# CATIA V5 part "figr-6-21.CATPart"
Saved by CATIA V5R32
Part number: Part1
Bounding box of the stored display mesh (mm): x 0 to 150, y -70 to 70, z -150 to 69.804
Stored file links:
  D:\PROJECTS\Project 2022\CATIA V5 6R 2022\Resources\Part Files\c06_catia_v5_6r2022_prt\figr-6-21.CATPart
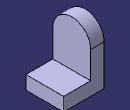
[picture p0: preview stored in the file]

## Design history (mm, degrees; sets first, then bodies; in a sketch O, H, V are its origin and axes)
Body1 (main body)
  Sketch1 on yz-plane, origin (0, 0, 0), H (0, 1, 0), V (0, 0, 1)
    arc A1 centre (0, 0) radius 70 from (70, 0) to (-70, 0) ccw
    point P1 (70, 0)
    point P2 (-70, 0)
    line L1 (-70, 0) -> (-70, -150)
    line L2 (-70, -150) -> (70, -150)
    line L3 (70, -150) -> (70, 0)
    construction circle A2 centre (0, 0) radius 37.5
    radius A1 = 70
    radius A2 = 37.5
    distance O L2 = 150
    coincidence: P1 H, P2 H
    tangency: L1 A1, L3 A1
    horizontal: L2 H
  Pad1: profile Sketch1, direction (1, 0, 0), length 50
  Sketch2 on face of Pad1, origin (50, 0, 0), H (0, 1, 0), V (0, 0, 1)
    line L1 (-70, -150) -> (70, -150)
    line L2 (70, -150) -> (70, -100)
    line L3 (70, -100) -> (-70, -100)
    line L4 (-70, -100) -> (-70, -150)
    reference projected line E1 (-70, -150) -> (70, -150) from edge [face of Pad1 | face of Pad1]
    reference projected line E2 (-70, 0) -> (-70, -150) from edge [face of Pad1 | face of Pad1]
    reference projected line E3 (70, -150) -> (70, 0) from edge [face of Pad1 | face of Pad1]
    length L2 = 50
    horizontal: L1 H, L3 H
    vertical: L2 V, L4 V
    coincidence: L1 E1, E2 L4, L2 E3
  Pad2: profile Sketch2, direction (1, 0, 0), length 100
